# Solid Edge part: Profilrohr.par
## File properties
Username: bmolnar
Dokumentum tartalom típus: 0
Author: bmolnar
Last saved by: bmolnar
Revision: 83
Sűrűség: 0,000 kg/m^3
Pontosság: 0,990
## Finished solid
Body 1: solid body, 63 faces, 178 edges, 112 vertices.
  Faces by surface: cylinder 33, plane 30
  Edges by curve: line 112, circle 66
Bounding box of the edges (mm): 36.000 x 53.400 x 36.000, from (-18, -44.15, -18) to (18, 9.25, 18).
Cylindrical faces by radius (mm): R0.2 x12, R0.5 x12, R3.775 x4, R4.5 x4, R10 x1
Planar faces by outward normal: +x 7, +y 1, +z 7, -x 7, -y 1, -z 7
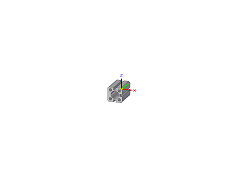
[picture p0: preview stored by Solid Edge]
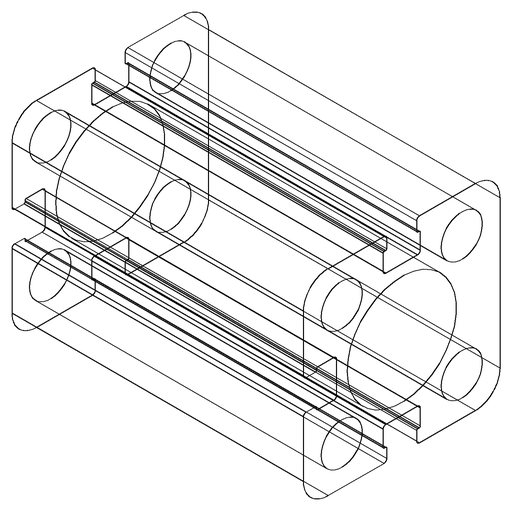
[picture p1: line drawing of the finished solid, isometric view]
